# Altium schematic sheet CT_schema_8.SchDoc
size 287 x 160 mm
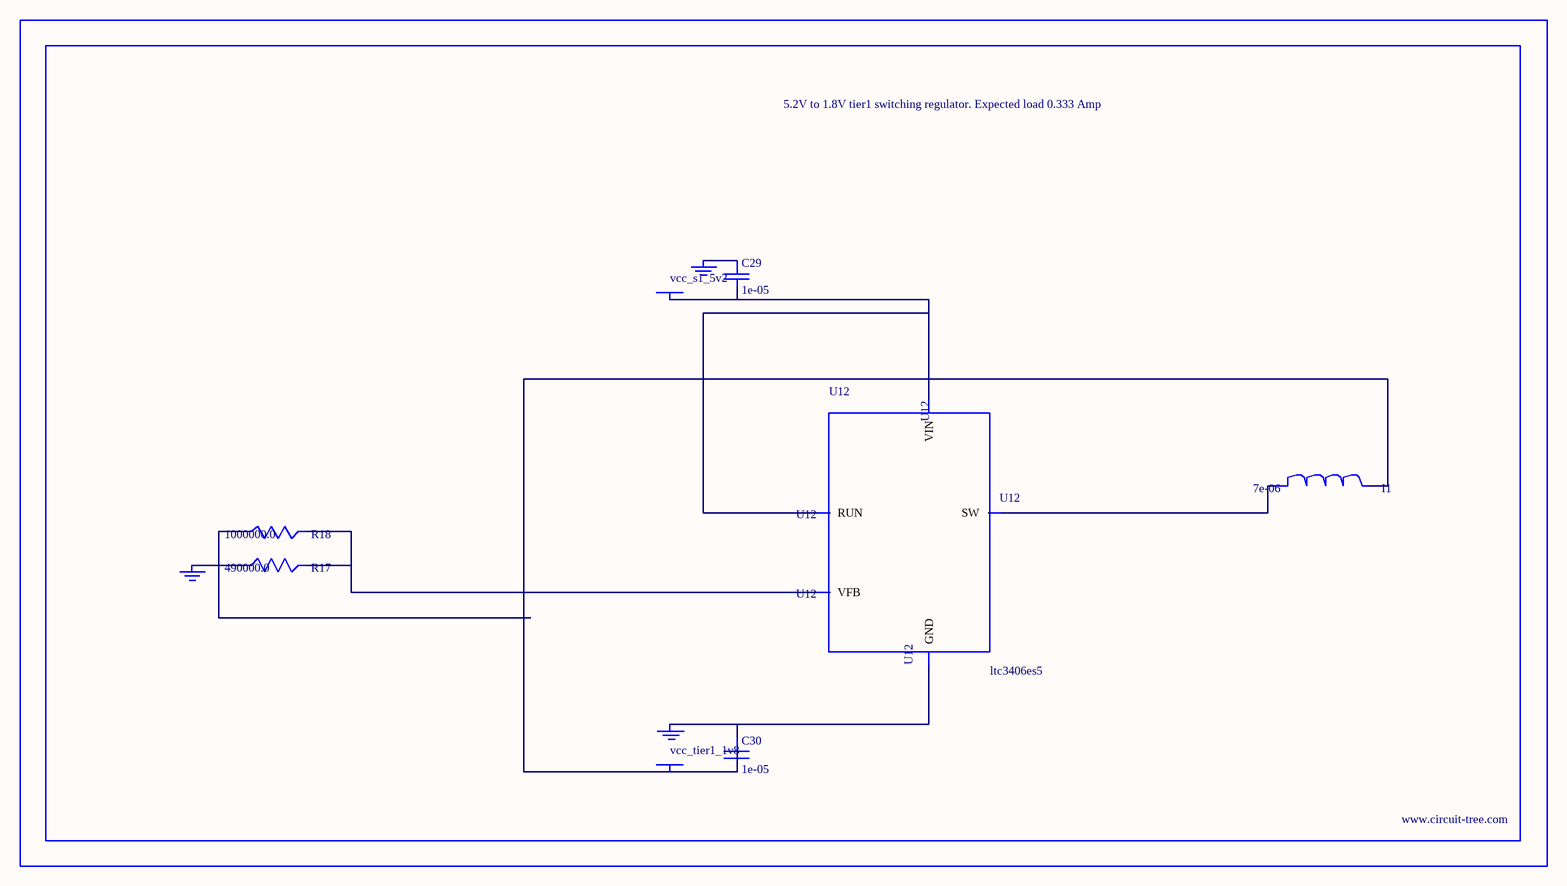
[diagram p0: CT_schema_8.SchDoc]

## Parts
BORDER7  (no value)
C29  1e-05  [C0805]
C30  1e-05  [C0805]
GND_INSTANCE_7_0  (no value)
GND_INSTANCE_7_1  (no value)
GND_INSTANCE_7_2  (no value)
I1  7e-06  [DR1040]
POWER_INSTANCE_7_0  vcc_tier1_1v8
POWER_INSTANCE_7_1  vcc_s1_5v2
R17  490000.0  [R0603]
R18  1000000.0  [R0603]
U12  ltc3406es5  [TSOT-23-5]

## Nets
NetC29_1: C29.1 GND_INSTANCE_7_1.0(GND)
NetC29_2: C29.2 POWER_INSTANCE_7_1.0(PWR) U12.1(RUN) U12.4(VIN)
NetC30_1: C30.1 GND_INSTANCE_7_0.0(GND) U12.2(GND)
NetC30_2: C30.2 I1.2 POWER_INSTANCE_7_0.0(PWR) R18.1
NetGND_INSTANCE_7_2_0: GND_INSTANCE_7_2.0(GND) R17.1
NetI1_1: I1.1 U12.3(SW)
NetR17_2: R17.2 R18.2 U12.5(VFB)

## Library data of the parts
BORDER7 = BORDER_PAGE7
C29 C30 = C0805C106K8RACTU
GND_INSTANCE_7_0-GND_INSTANCE_7_2 = GND
I1 = DR1040-7R0-R
POWER_INSTANCE_7_0 POWER_INSTANCE_7_1 = PWR
R17 = R17
R18 = RC0603JR-071ML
